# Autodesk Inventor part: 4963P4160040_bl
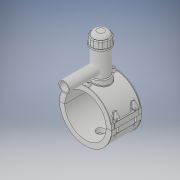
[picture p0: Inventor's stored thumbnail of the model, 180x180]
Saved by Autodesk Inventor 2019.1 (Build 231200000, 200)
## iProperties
Created: 2017-07
Part Number: 4963P4160040_bl
Material: Generic
Document SubType Name: Modeling
Designer: KIM
Density: 1 g/cm^3
Appearance: Default
Author: KIM
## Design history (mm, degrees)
derived "4963P4.ipt"
feature "Solid1::4963P4.ipt" dims "ScaleForDerivedMember" = 10
feature "Solid2::4963P4.ipt" dims "ScaleForDerivedMember" = 10
feature "Solid3::4963P4.ipt" dims "ScaleForDerivedMember" = 10
tag "TaggingFeature1"
body "Solid1"
body "Solid2"
body "Solid3"
other parameters: "d2" = 199 [user parameter], "d4" = 118 [user parameter], "d5" = 0 [user parameter], "d6" = 0.1 [user parameter], "d8" = 0 [user parameter], "d19" = 6 [user parameter], "d20" = 6 [user parameter], "d21" = 70.8 [user parameter], "d23" = 0 [user parameter], "d24" = 35.4 [user parameter], "d26" = 0 [user parameter], "d27" = 3 [user parameter], "d28" = 3 [user parameter], "d29" = 3 [user parameter], "d30" = 53.33333 [user parameter], "d31" = 6 [user parameter], "d32" = 0 [user parameter], "d33" = 0 [user parameter], "d34" = 0.6 [user parameter], "d40" = 101.504 [user parameter], "d41" = 72 [user parameter], "d43" = 0 [user parameter], "d45" = 0 [user parameter], "d47" = 168.4 [user parameter], "d70" = 15 [user parameter], "d72" = 0 [user parameter], "d73" = 6 [user parameter], "d75" = 5 [user parameter], "d76" = 0 [user parameter], "d77" = 8 [user parameter], "d79" = 15 [user parameter], "d80" = 47.2 [user parameter], "d82" = 5 deg [user parameter], "d84" = 4 [user parameter], "d85" = 14 [user parameter], "d86" = 0 [user parameter], "d87" = 3 [user parameter], "d88" = 0 [user parameter], "d89" = 1 [user parameter], "d90" = 1 [user parameter], "d91" = 94.4 [user parameter], "d92" = 0 [user parameter], "d93" = 0.5 [user parameter], "d94" = 84.21053 [user parameter], "d96" = 199.104 [user parameter], "d97" = 2.36 [user parameter], "d98" = 0 [user parameter], "d102" = 1.6 [user parameter], "d120" = 140 deg [user parameter], "d121" = 24.228 [user parameter], "d122" = 20 deg [user parameter], "d123" = 390.4 [user parameter], "d124" = 117.12 [user parameter], "d126" = 0 [user parameter], "d143" = 164.8 [user parameter], "d145" = 27.07692 [user parameter], "d149" = 2.4 [user parameter], "d150" = 29.78462 [user parameter], "d153" = 118 [user parameter], "d154" = 0 [user parameter], "d156" = 97.6 [user parameter], "d157" = 160 deg [user parameter], "d159" = 7.04 [user parameter], "d161" = 2.4 [user parameter], "d162" = 70.8 [user parameter], "d163" = 0 [user parameter], "d167" = 16 [user parameter], "d168" = 95.21951 [user parameter], "d170" = 3.75 [user parameter], "d172" = 0 [user parameter], "d173" = 1 [user parameter], "d176" = 20 deg [user parameter], "d177" = 11.2 [user parameter], "d178" = 35.2 [user parameter], "d180" = 0 [user parameter], "d183" = 14.08 [user parameter], "d184" = 8.96 [user parameter], "d185" = 38.35 [user parameter], "d186" = 38.35 [user parameter], "d187" = 97.6 [user parameter], "d188" = 10.56 [user parameter], "d189" = 11.2 [user parameter], "d190" = 0 [user parameter], "d191" = 146.4 [user parameter], "d193" = 8 [user parameter], "d194" = 4.13 [user parameter], "d195" = 90 deg [user parameter], "d197" = 0 [user parameter], "d199" = 0 [user parameter], "d200" = 17.6 [user parameter], "d202" = 0 [user parameter], "d203" = 177 [user parameter], "d204" = 68.4 [user parameter], "d205" = 50.4 [user parameter], "d206" = 61.2 [user parameter], "d207" = 132.75 [user parameter], "d208" = 138.06 [user parameter], "d209" = 164.61 [user parameter], "d210" = 61.92 [user parameter], "d211" = 72 [user parameter], "d212" = 57.6 [user parameter], "d213" = 36 [user parameter], "d216" = 0 [user parameter], "d217" = 16 [user parameter], "d218" = 16 [user parameter], "d219" = 3.2 [user parameter], "d224" = 0 [user parameter], "d227" = 32 [user parameter], "d228" = 142 [user parameter], "d230" = 3.2 [user parameter], "B_" = 199 [user parameter], "L_" = 118 [user parameter], "d_t" = 6 [user parameter], "H_2" = 177 [user parameter], "H_" = 142 [user parameter], "d1" = 195.2 [user parameter], "d148" = 2.4 [user parameter], "d160" = 2.4 [user parameter], "d169" = 3.75 [user parameter], "d192" = 8 [user parameter]
